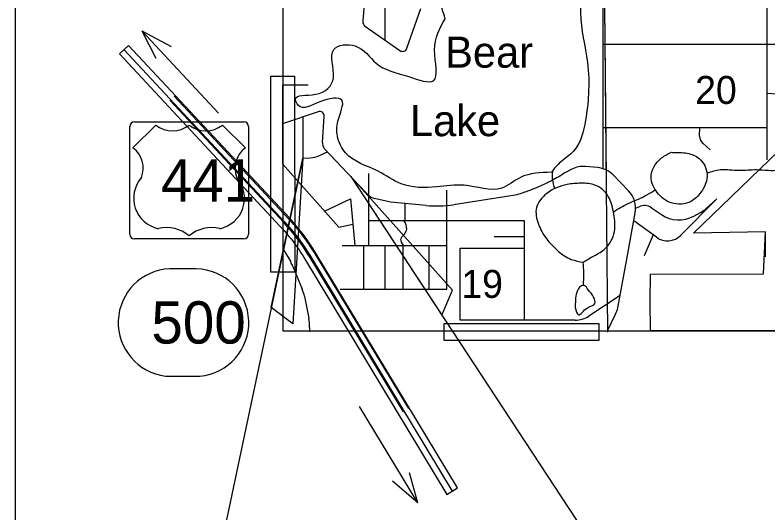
# Model space of a CAD drawing. Extents: x 2157516 to 2331756, y 2153820 to 2265756.
# Drawn here: x 2224044 to 2249249, y 2184545 to 2201230 of the extents above; entities that cross this region are included whole.
import ezdxf

# ---------------------------------------------------------------- set-up
doc = ezdxf.new("R2010")
doc.units = 0
for name, color, linetype in [('Default', 7, 'Continuous'), ('LeaderLine_dp', 7, 'Continuous'), ('MapOutline_dp', 7, 'Continuous')]:
    doc.layers.add(name, color=color, linetype=linetype)

msp = doc.modelspace()

# ---------------------------------------------------------------- linework, layer by layer
at = {"layer": 'Default'}
for p, q in [((2243735, 2196078), (2243735, 2212780)), ((2249218, 2196375), (2249218, 2203067)), ((2236435, 2200382), (2236435, 2202667)), ((2235743, 2201749), (2235687, 2201031)), ((2237159, 2200118), (2237624, 2201446)), ((2243775, 2201524), (2243876, 2190600)), ((2228285, 2200706), (2230857, 2197947)), ((2228285, 2200706), (2229266, 2200173)), ((2228285, 2200706), (2228758, 2199783)), ((2235776, 2200845), (2236922, 2200041)), ((2227840, 2200213), (2227535, 2199929)), ((2227535, 2199929), (2227840, 2200213)), ((2243735, 2200251), (2253136, 2200251)), ((2232997, 2198875), (2232997, 2196239)), ((2233861, 2198875), (2233029, 2198875)), ((2229374, 2198515), (2233202, 2194406)), ((2249218, 2198609), (2250448, 2198535)), ((2229221, 2198373), (2233050, 2194264)), ((2234190, 2197991), (2232997, 2197581)), ((2228037, 2197649), (2231704, 2197649)), ((2233677, 2197815), (2233677, 2196432)), ((2234338, 2196955), (2234397, 2197832)), ((2227881, 2193884), (2227881, 2197493)), ((2228755, 2197545), (2227985, 2196783)), ((2228755, 2197545), (2228755, 2197545)), ((2229871, 2197541), (2229871, 2197541)), ((2231756, 2196783), (2230987, 2197545)), ((2231861, 2197493), (2231861, 2193884)), ((2243735, 2197456), (2249218, 2197456)), ((2246963, 2197168), (2246966, 2197456)), ((2247317, 2196712), (2247068, 2196931)), ((2234231, 2196519), (2234500, 2196644)), ((2235777, 2195296), (2234389, 2196761)), ((2233677, 2196432), (2233921, 2196443)), ((2246020, 2196630), (2246058, 2196624)), ((2232997, 2196239), (2234881, 2194123)), ((2243542, 2196118), (2243144, 2196153)), ((2235882, 2193505), (2235882, 2195920)), ((2242685, 2196061), (2242450, 2195938)), ((2244584, 2195338), (2244066, 2195870)), ((2235866, 2195203), (2235777, 2195296)), ((2238498, 2193050), (2238498, 2195364)), ((2240786, 2195189), (2238724, 2194875)), ((2234400, 2194663), (2235271, 2195075)), ((2235271, 2195075), (2235417, 2193505)), ((2236614, 2194960), (2236076, 2195083)), ((2237807, 2194848), (2236614, 2194960)), ((2237105, 2194349), (2237105, 2194914)), ((2247539, 2195074), (2246334, 2193849)), ((2247196, 2194758), (2247539, 2195074)), ((2244820, 2194753), (2244935, 2194806)), ((2245346, 2194774), (2245684, 2194544)), ((2244520, 2193050), (2244807, 2194607)), ((2246766, 2194490), (2246988, 2194610)), ((2234881, 2194123), (2235350, 2194224)), ((2235882, 2194349), (2241083, 2194349)), ((2241083, 2194349), (2241083, 2191005)), ((2245521, 2193783), (2244757, 2194339)), ((2245406, 2193867), (2245100, 2193159)), ((2249172, 2193132), (2249172, 2193933)), ((2231704, 2193728), (2228037, 2193728)), ((2240083, 2193808), (2241083, 2193808)), ((2233022, 2193389), (2233272, 2192955)), ((2234992, 2193505), (2238498, 2193505)), ((2235720, 2192045), (2235720, 2193505)), ((2236431, 2192045), (2236431, 2193505)), ((2237038, 2192045), (2237038, 2193505)), ((2237912, 2192045), (2237912, 2193505)), ((2238943, 2191005), (2238943, 2193413)), ((2238943, 2193413), (2241083, 2193413)), ((2233881, 2193163), (2237033, 2187934)), ((2234059, 2193270), (2237212, 2188042)), ((2238498, 2192045), (2238498, 2193050)), ((2244221, 2191423), (2244520, 2193050)), ((2230106, 2192727), (2229222, 2192727)), ((2233345, 2192806), (2233661, 2192039)), ((2234928, 2192045), (2238498, 2192045)), ((2233731, 2191804), (2233876, 2191069)), ((2244297, 2191833), (2243254, 2191143)), ((2243873, 2190644), (2244149, 2191205)), ((2242794, 2191005), (2238943, 2191005)), ((2233897, 2190760), (2233897, 2190617)), ((2229082, 2189131), (2230232, 2189131)), ((2237526, 2184883), (2235579, 2188113)), ((2237526, 2184883), (2237254, 2185885)), ((2237526, 2184883), (2236677, 2185607)), ((2238501, 2185167), (2238857, 2185382)), ((2238501, 2185167), (2238857, 2185382))]:
    msp.add_line(p, q, dxfattribs=at)
for points in [[(2233007, 2222724), (2233007, 2190644)], [(2265958, 2190664), (2245319, 2190652), (2245307, 2191654), (2245319, 2192549), (2249099, 2192561), (2249167, 2193966), (2246762, 2193921), (2254372, 2201275), (2253227, 2201282), (2253233, 2203055), (2252119, 2203079), (2252103, 2204383), (2254726, 2204410), (2254718, 2210303), (2257483, 2210276), (2257499, 2215340), (2253665, 2215400), (2253649, 2218097), (2254852, 2218113), (2254836, 2220906), (2257403, 2220890), (2257403, 2222724)], [(2243831, 2215454), (2243775, 2201524), (2243829, 2195744)], [(2238857, 2185382), (2234089, 2193289), (2234027, 2193391), (2233961, 2193493), (2233895, 2193592), (2233827, 2193692), (2233756, 2193791), (2233685, 2193886), (2233612, 2193982), (2233536, 2194077), (2233459, 2194170), (2233380, 2194262), (2233301, 2194351), (2233229, 2194429), (2227840, 2200213)], [(2227535, 2199929), (2232923, 2194147), (2232991, 2194072), (2233067, 2193988), (2233141, 2193901), (2233213, 2193814), (2233283, 2193726), (2233352, 2193636), (2233420, 2193545), (2233486, 2193453), (2233550, 2193359), (2233613, 2193265), (2233674, 2193170), (2233733, 2193073), (2238501, 2185167)], [(2227687, 2200071), (2233076, 2194288), (2233146, 2194212), (2233224, 2194125), (2233300, 2194035), (2233374, 2193946), (2233447, 2193854), (2233519, 2193761), (2233588, 2193668), (2233656, 2193573), (2233723, 2193476), (2233787, 2193379), (2233850, 2193281), (2233911, 2193181), (2238679, 2185274)], [(2233007, 2190644), (2265958, 2190644)]]:
    msp.add_lwpolyline(points, dxfattribs=at)
for points in [[(2232603, 2199176), (2233401, 2199176), (2233409, 2192619), (2232611, 2192619)], [(2238412, 2190889), (2243582, 2190889), (2243582, 2190328), (2238412, 2190328)]]:
    msp.add_lwpolyline(points, close=True, dxfattribs=at)
for centre, radius, start, end in [((2235895, 2201015), 208, 175.5558, 234.9807), ((2237012, 2200169), 156, 234.9809, 340.6992), ((2234241, 2197843), 156, 356.1574, 108.933), ((2228037, 2197493), 156, 90, 180), ((2231704, 2197493), 156, 0, 90), ((2229315, 2198244), 896, 231.2915, 308.3626), ((2230427, 2198244), 896, 231.6374, 308.7085), ((2247275, 2197164), 312, 179.2363, 228.652), ((2234649, 2196934), 312, 176.1574, 213.5032), ((2227483, 2196096), 851, 338.3056, 53.8199), ((2232259, 2196096), 851, 126.1801, 201.6944), ((2233882, 2197275), 833, 272.7034, 294.8141), ((2243072, 2195324), 833, 84.9943, 117.6686), ((2243470, 2195289), 833, 44.2479, 84.9942), ((2229059, 2195093), 1044, 138.7831, 258.2378), ((2230683, 2195093), 1044, 281.7622, 41.2169), ((2236168, 2195489), 416, 223.4492, 257.1956), ((2243988, 2194757), 833, 349.5783, 44.2477), ((2238158, 2198579), 3747, 264.6256, 278.6735), ((2245112, 2194429), 416, 55.7714, 115.1072), ((2246491, 2195525), 1041, 298.4815, 312.5633), ((2228176, 2189723), 6870, 31.0886, 42.9794), ((2246270, 2195404), 1041, 235.7714, 298.4821), ((2228176, 2189723), 6662, 31.0886, 42.9794), ((2228037, 2193884), 156, 180, 270), ((2229123, 2192943), 1162, 49.9101, 103.7765), ((2230619, 2192943), 1162, 76.2235, 130.0899), ((2231704, 2193884), 156, 270, 360), ((2245889, 2194287), 625, 233.9246, 315.4509), ((2232190, 2192331), 1249, 22.3567, 29.9909), ((2229303, 2190923), 1806, 92.5588, 262.9755), ((2230065, 2190925), 1803, 275.316, 88.7032), ((2232505, 2191564), 1249, 11.1036, 22.3567), ((2243402, 2191573), 833, 333.7838, 349.5783), ((2242794, 2191837), 833, 270, 303.4934), ((2232650, 2190828), 1249, 356.8777, 11.1036)]:
    msp.add_arc(centre, radius, start, end, dxfattribs=at)
for points in [[(2238441, 2201107), (2238245, 2201773), (2237750, 2202631), (2236588, 2203077), (2236704, 2203960), (2237225, 2204885), (2237808, 2205501), (2238891, 2204968), (2239969, 2204431), (2241123, 2203685), (2242227, 2203248), (2242822, 2202794), (2242974, 2201315), (2243208, 2199644), (2243241, 2198575), (2243141, 2197706), (2242740, 2196670), (2242305, 2196302), (2241998, 2195962)], [(2241998, 2195962), (2240961, 2195787), (2240336, 2195433), (2239074, 2195525), (2238162, 2195471), (2236971, 2195575), (2236196, 2195995), (2235109, 2196608), (2234834, 2197174), (2234851, 2197670), (2234988, 2198373), (2234251, 2198319), (2233526, 2198211), (2233435, 2198390), (2234105, 2198573), (2234701, 2199127), (2234713, 2200077), (2235434, 2200194), (2236134, 2199615), (2237229, 2199165), (2238054, 2199027), (2238091, 2200048), (2238441, 2201107)], [(2246058, 2196624), (2246545, 2196599), (2246949, 2196420), (2247211, 2195903), (2247007, 2195291), (2246678, 2194987), (2246012, 2194937), (2245545, 2195278), (2245337, 2195795), (2245687, 2196440), (2246020, 2196630)], [(2242450, 2195938), (2242226, 2195802), (2242000, 2195677), (2241847, 2195600), (2241641, 2195504), (2241361, 2195387), (2241198, 2195325), (2241008, 2195259), (2240786, 2195189)], [(2242108, 2195414), (2242094, 2195487), (2242031, 2195820), (2242054, 2196024)], [(2247209, 2195935), (2247664, 2196049), (2248273, 2196028), (2248868, 2196049), (2249256, 2196028), (2249631, 2196028)], [(2243059, 2192947), (2243378, 2193134), (2243769, 2193376), (2244110, 2193979), (2244089, 2194557), (2243902, 2195152), (2243482, 2195522), (2242987, 2195593), (2242525, 2195551), (2241843, 2195252), (2241502, 2194781), (2241564, 2194224), (2241830, 2193746), (2242011, 2193525)], [(2244074, 2194637), (2244565, 2194912), (2244911, 2195062), (2245478, 2195369)], [(2237047, 2193505), (2236964, 2193721), (2237076, 2193887), (2237155, 2194058), (2237063, 2194349)], [(2242011, 2193525), (2242234, 2193309), (2242662, 2193043), (2243059, 2192947)], [(2243069, 2192176), (2243089, 2192589), (2243059, 2192947)], [(2242790, 2191434), (2242906, 2191188), (2243206, 2191422), (2243456, 2191563), (2243414, 2191780), (2243231, 2192026), (2243098, 2192167), (2243010, 2192151), (2242835, 2191901), (2242817, 2191820)], [(2242817, 2191820), (2242812, 2191783), (2242809, 2191747), (2242804, 2191673), (2242798, 2191524), (2242795, 2191482), (2242790, 2191434)]]:
    msp.add_spline(points, degree=3, dxfattribs=at)
at = {"layer": 'LeaderLine_dp'}
for p, q in [((2233677, 2196432), (2228628, 2172526)), ((2235280, 2195821), (2250505, 2172636))]:
    msp.add_line(p, q, dxfattribs=at)
for points in [[(2233677, 2196432), (2233348, 2190881), (2232622, 2191435)], [(2235280, 2195821), (2238332, 2191172), (2238685, 2192015)]]:
    msp.add_lwpolyline(points, close=True, dxfattribs=at)
at = {"layer": 'MapOutline_dp'}
msp.add_lwpolyline([(2224044, 2180484), (2265958, 2180484), (2265958, 2222724), (2224044, 2222724)], close=True, dxfattribs=at)

# ---------------------------------------------------------------- texts
at = {"layer": 'Default'}
for s, height, p in [('Bear', 1040.9, (2238444, 2199466)), ('20', 936.8, (2246811, 2198251)), ('Lake', 1040.9, (2237264, 2197171)), ('19', 936.8, (2238984, 2191752))]:
    msp.add_text(s, height=height, rotation=360, dxfattribs=at).set_placement(p)
for s, p in [('441', (2228926, 2194979)), ('500', (2228608, 2190221))]:
    msp.add_text(s, height=1415.7, dxfattribs=at).set_placement(p)

doc.saveas('drawing.dxf')
